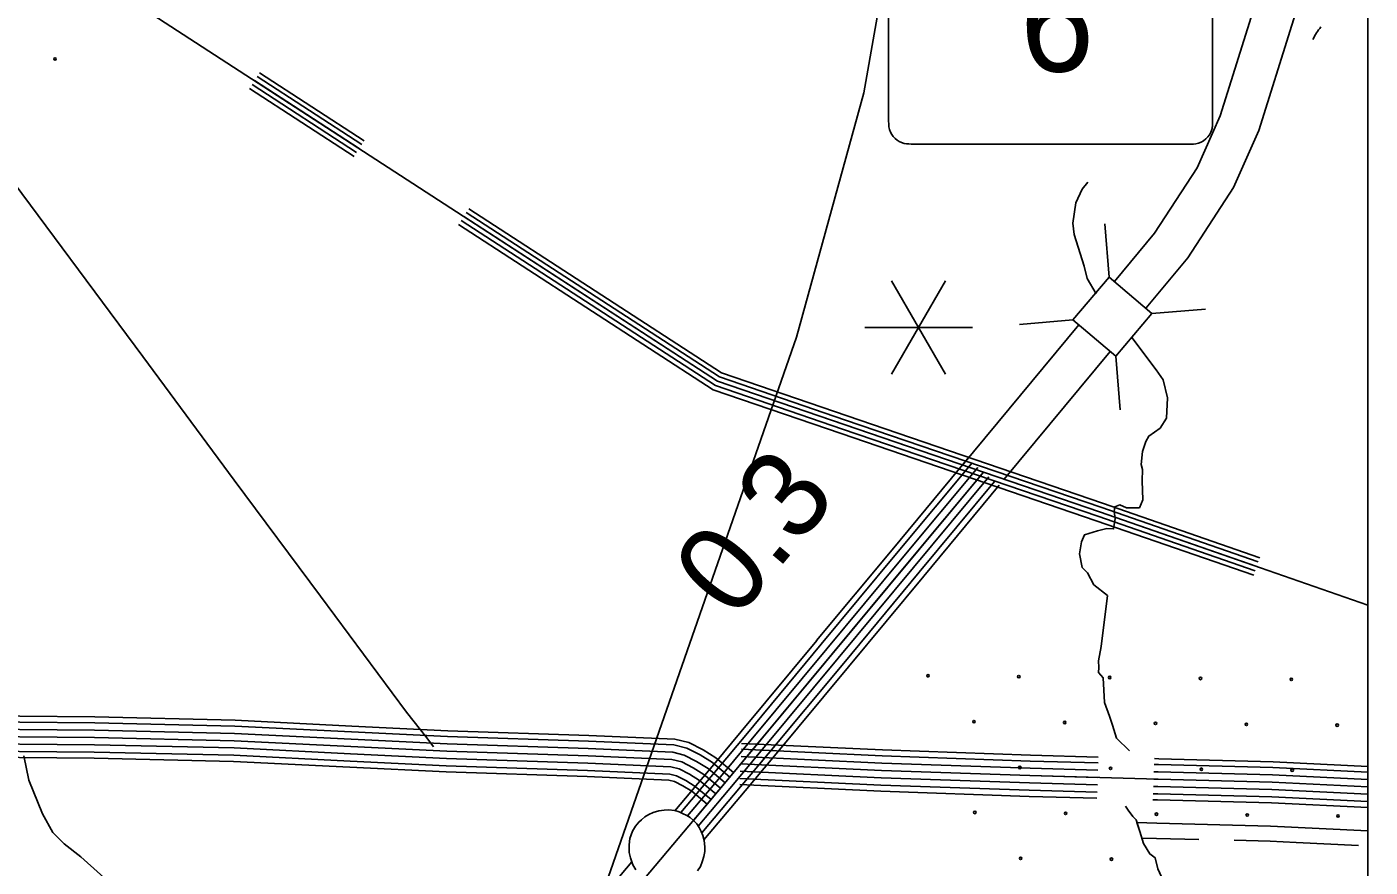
# Model space of a CAD drawing. Extents: x 1577619 to 1828281, y 483481 to 598136.
# Drawn here: x 1689939 to 1695627, y 517507 to 521065 of the extents above; entities that cross this region are included whole.
import ezdxf

# ---------------------------------------------------------------- set-up
doc = ezdxf.new("R2010")
doc.units = 0
for name, color, linetype in [('DESIGN - EROSION CONTROL - Devices', 7, 'Continuous'), ('DESIGN - ROW - Slope Lines', 7, 'Continuous'), ('DESIGN - SHEET - Linework', 7, 'Continuous'), ('DESIGN - TRAFFIC CONTROL PERMANENT - Signalization', 7, 'Continuous'), ('DESIGN - TRANSPORTATION - Text', 7, 'Continuous'), ('SURVEY - CENTERLINE - Preliminary', 7, 'Continuous'), ('SURVEY - CENTERLINE - Preliminary Text', 7, 'Continuous'), ('SURVEY - CONTROL with Text', 7, 'Continuous'), ('SURVEY - DRAINAGE - Area Shapes', 7, 'Continuous'), ('SURVEY - DRAINAGE - Bridge Deck with Text', 7, 'Continuous'), ('SURVEY - DRAINAGE - Natural Features', 7, 'Continuous'), ('SURVEY - DRAINAGE - Storm Sewer', 7, 'Continuous'), ('SURVEY - VEGETATION - Features with Text', 7, 'Continuous')]:
    doc.layers.add(name, color=color, linetype=linetype)

msp = doc.modelspace()

# ---------------------------------------------------------------- linework, layer by layer
at = {"layer": 'DESIGN - EROSION CONTROL - Devices'}
for centre in [(1690058, 520929.4), (1693755.1, 518317.3), (1694139.6, 518313.6), (1694524.2, 518309.8), (1694908.7, 518306.1), (1695293.3, 518302.4), (1693949.2, 518123.1), (1694333.8, 518119.4), (1694718.3, 518115.7), (1695102.9, 518111.9), (1695487.4, 518108.2), (1694143.4, 517929), (1694527.9, 517925.3), (1694912.5, 517921.5), (1695297, 517917.8), (1693953, 517738.6), (1694337.5, 517734.9), (1694722.1, 517731.1), (1695106.6, 517727.4), (1695491.2, 517723.7), (1694147.1, 517544.4), (1694531.6, 517540.7)]:
    msp.add_circle(centre, 5.28, dxfattribs=at)
at = {"layer": 'DESIGN - ROW - Slope Lines'}
for p, q in [((1693587.2, 521509.8), (1693587.2, 520678.1)), ((1694960.1, 520679.5), (1694960.1, 521499.4)), ((1693693.6, 520568.7), (1694850.2, 520568.7))]:
    msp.add_line(p, q, dxfattribs=at)
for centre, radius, start, end in [((1693861.3, 520677.3), 274.1, 179.8528, 189.8964), ((1694013, 520684.2), 947.1, 357.7373, 359.7128), ((1693677.9, 520659.3), 91.3, 198.5724, 254.4318), ((1694871.7, 520657.1), 89.4, 280.9255, 342.7446), ((1694890.7, 520648.3), 68.6, 345.0701, 358.7436), ((1693697.5, 520931.1), 362.4, 263.0109, 269.3986), ((1694860.7, 521103.5), 534.8, 268.8795, 272.9943)]:
    msp.add_arc(centre, radius, start, end, dxfattribs=at)
at = {"layer": 'DESIGN - SHEET - Linework'}
msp.add_lwpolyline([(1669171.5, 526510.7), (1695618, 526510.7), (1695618, 508119.9), (1669171.5, 508119.9)], close=True, dxfattribs=at)
at = {"layer": 'DESIGN - TRAFFIC CONTROL PERMANENT - Signalization'}
for q in [(1693600.8, 519989.3), (1693828.9, 519989.3), (1693486.8, 519791.7), (1693600.8, 519594.2), (1693942.9, 519791.8), (1693828.9, 519594.2)]:
    msp.add_line((1693714.9, 519791.7), q, dxfattribs=at)
at = {"layer": 'DESIGN - TRANSPORTATION - Text'}
for points in [[(1694466.6, 519935.3), (1694428.4, 519999.1), (1694416.4, 520051.7), (1694382.9, 520159.5), (1694373.4, 520185.8), (1694368.6, 520233.7), (1694380.5, 520319.9), (1694406.9, 520377.4), (1694432.1, 520407.7)], [(1694514.5, 518657.9), (1694457.3, 518702.9), (1694429.8, 518753.4), (1694408, 518775.8), (1694396.7, 518834.2), (1694405.3, 518884.2), (1694417.7, 518914.2), (1694472, 518931.6), (1694512.3, 518941.2), (1694540.3, 518938.9), (1694546.9, 518982.9), (1694543.2, 519013.1), (1694545.5, 519033.2), (1694567.6, 519040.9), (1694595.6, 519028.5), (1694625.7, 519028.2), (1694649.7, 519027.9), (1694664.2, 519061.8), (1694661.1, 519142.2), (1694663.7, 519190.4), (1694657.9, 519212.5), (1694662.6, 519266.7), (1694677.1, 519308.7), (1694689.5, 519332.6), (1694738, 519366.2), (1694764.6, 519408), (1694769.2, 519493.8), (1694750.1, 519570.4), (1694721.4, 519613.5), (1694617.8, 519749.4)], [(1694514.5, 518657.9), (1694487.7, 518441.8), (1694476.8, 518380), (1694478.7, 518352.8), (1694476.3, 518331.2), (1694496.1, 518308.9), (1694502.7, 518204.1), (1694522.7, 518146), (1694535.4, 518107.9), (1694553.6, 518053.4), (1694608, 517999.2)], [(1689925.9, 517977.9), (1689946.8, 517875.4), (1690005.3, 517732.4), (1690048.5, 517653.7), (1690096, 517605.1), (1690167.5, 517550.2), (1690320.1, 517414.2)], [(1694591, 517765.1), (1694602.2, 517748.3), (1694621.9, 517722), (1694635.8, 517707.8), (1694651.3, 517657.5), (1694666.8, 517607.2), (1694694.3, 517562.8), (1694716.1, 517546.5), (1694727.7, 517500.3)]]:
    msp.add_lwpolyline(points, dxfattribs=at)
at = {"layer": 'SURVEY - CENTERLINE - Preliminary'}
for points in [[(1699664.1, 538980.8), (1699319.1, 538409.9), (1698972.3, 537842.5), (1695481.3, 532468.9), (1695357.3, 532233.8), (1695216.5, 531898.8), (1695066.9, 531469.7), (1694585.2, 529330), (1694371.3, 528155.8), (1694207.2, 527174.4), (1693664.5, 521961.3), (1693575.1, 521307.5), (1693482.8, 520785.8), (1693198.2, 519751.4), (1691958.7, 516195.2)], [(1699664.1, 538980.8), (1699319.1, 538409.9), (1698972.3, 537842.5), (1695481.3, 532468.9), (1695357.3, 532233.8), (1695216.5, 531898.8), (1695066.9, 531469.7), (1694585.2, 529330), (1694371.3, 528155.8), (1694207.2, 527174.4), (1693664.5, 521961.3), (1693575.1, 521307.5), (1693482.8, 520785.8), (1693198.2, 519751.4), (1691958.7, 516195.2)], [(1694138.1, 526510.7), (1693664.5, 521961.3), (1693575.1, 521307.5), (1693482.8, 520785.8), (1693198.2, 519751.4), (1691958.7, 516195.2)], [(1694138.1, 526510.7), (1693664.5, 521961.3), (1693575.1, 521307.5), (1693482.8, 520785.8), (1693198.2, 519751.4), (1691958.7, 516195.2)]]:
    msp.add_lwpolyline(points, dxfattribs=at)
at = {"layer": 'SURVEY - CENTERLINE - Preliminary Text'}
for points in [[(1695269.4, 521574.5), (1694992.2, 520687.8), (1694894.5, 520468.7), (1694713.7, 520191.2), (1694544.4, 519986.7)], [(1695434.9, 521519.3), (1695155.6, 520626), (1695048.2, 520385), (1694854.4, 520087.6), (1694679.2, 519876)], [(1694392.8, 519803.6), (1693899.1, 519207.3)], [(1694525.6, 519690.5), (1694077.9, 519149.7)], [(1693922.4, 519235.5), (1693602.8, 518851)], [(1693941.4, 519219.7), (1693621.8, 518835.2)], [(1693965.3, 519199.9), (1693645.7, 518815.4)], [(1693989.1, 519180.1), (1692913.8, 517886.3), (1692164.4, 516995.8)], [(1693989.1, 519180.1), (1693669.5, 518795.5)], [(1694013, 519160.2), (1693693.4, 518775.7)], [(1694036.8, 519140.4), (1693717.2, 518755.9)], [(1694056.6, 519124), (1693737, 518739.5)], [(1693602.9, 518851), (1693283.2, 518466.5)], [(1693621.9, 518835.2), (1693302.3, 518450.7)], [(1693645.7, 518815.4), (1693326.1, 518430.9)], [(1693669.5, 518795.6), (1693349.9, 518411)], [(1693693.4, 518775.7), (1693373.8, 518391.2)], [(1693717.2, 518755.9), (1693397.6, 518371.4)], [(1693737, 518739.5), (1693417.4, 518355)], [(1693283.3, 518466.5), (1692963.7, 518082)], [(1693302.3, 518450.7), (1692982.7, 518066.2)], [(1693326.1, 518430.9), (1693006.5, 518046.3)], [(1693349.9, 518411), (1693030.3, 518026.5)], [(1693373.8, 518391.2), (1693054.2, 518006.7)], [(1693397.6, 518371.4), (1693078, 517986.9)], [(1693417.4, 518355), (1693097.8, 517970.5)], [(1692963.7, 518082), (1692847.2, 517941.9), (1692682.4, 517746)], [(1692982.7, 518066.2), (1692866.2, 517926), (1692708.3, 517738.4)], [(1693006.5, 518046.4), (1692890, 517906.2), (1692736.5, 517723.8)], [(1693030.3, 518026.5), (1692913.8, 517886.3), (1692761.1, 517704.8)], [(1693054.2, 518006.7), (1692937.5, 517866.4), (1692781, 517680.4)], [(1693078, 517986.9), (1692961.3, 517846.5), (1692797.5, 517651.8)], [(1693097.8, 517970.5), (1692981, 517830), (1692806, 517622)], [(1692500.2, 517529.5), (1692321, 517316.6)]]:
    msp.add_lwpolyline(points, dxfattribs=at)
at = {"layer": 'SURVEY - CONTROL with Text'}
for points in [[(1680622.4, 518118.1), (1681890.1, 518100.2), (1682947.2, 518086.3), (1684160.8, 518074.9), (1685440.5, 518054.8), (1685817.6, 518049.3), (1686277.1, 518055), (1686923.1, 518057), (1687797.8, 518056.8), (1688568.2, 518065.6), (1689589.4, 518062.1), (1690225.2, 518056.1), (1690816.9, 518042.5), (1691310.2, 518017.8), (1691717.2, 517997.9), (1692314.9, 517978.2), (1692669.8, 517962.9), (1692711.8, 517952.4), (1692759.7, 517927.9), (1692805.6, 517899.3), (1692875.5, 517840.9)], [(1687034.2, 518143.7), (1687797.3, 518143.5), (1688567.9, 518152.3), (1689589.9, 518148.8), (1690226.6, 518142.8), (1690820.1, 518129.2), (1691314.5, 518104.4), (1691720.8, 518084.6), (1692318.2, 518064.9), (1692682.2, 518049.1), (1692742.4, 518034.2), (1692802.5, 518003.4), (1692856.5, 517969.8), (1692931.1, 517907.4)], [(1687034.6, 518119), (1687797.4, 518118.8), (1688568, 518127.6), (1689589.8, 518124.1), (1690226.2, 518118.1), (1690819.2, 518104.5), (1691313.3, 518079.7), (1691719.8, 518059.9), (1692317.2, 518040.2), (1692678.7, 518024.5), (1692733.7, 518010.9), (1692790.3, 517981.9), (1692842, 517949.7), (1692915.3, 517888.4)], [(1687035.2, 518088), (1687797.6, 518087.8), (1688568.1, 518096.6), (1689589.6, 518093.1), (1690225.7, 518087.1), (1690818.1, 518073.5), (1691311.7, 518048.7), (1691718.5, 518028.9), (1692316, 518009.2), (1692674.2, 517993.7), (1692722.8, 517981.6), (1692775, 517954.9), (1692823.8, 517924.5), (1692895.4, 517864.6)], [(1687035.7, 518056.9), (1687797.8, 518056.8), (1688568.2, 518065.6), (1689589.4, 518062.1), (1690225.2, 518056.1), (1690816.9, 518042.5), (1691310.2, 518017.8), (1691717.2, 517997.9), (1692314.9, 517978.2), (1692669.8, 517962.9), (1692711.8, 517952.4), (1692759.7, 517927.9), (1692805.6, 517899.3), (1692875.5, 517840.9)], [(1687036.3, 518025.9), (1687798, 518025.8), (1688568.4, 518034.6), (1689589.2, 518031), (1690224.7, 518025.1), (1690815.8, 518011.5), (1691308.7, 517986.8), (1691716, 517966.9), (1692313.7, 517947.3), (1692665.3, 517932), (1692700.9, 517923.2), (1692744.4, 517900.9), (1692787.4, 517874.2), (1692855.7, 517817.1)], [(1687036.8, 517994.9), (1687798.1, 517994.8), (1688568.5, 518003.6), (1689588.9, 518000), (1690224.2, 517994.1), (1690814.7, 517980.5), (1691307.1, 517955.9), (1691714.7, 517935.9), (1692312.5, 517916.3), (1692660.9, 517901.2), (1692689.9, 517894), (1692729.1, 517873.9), (1692769.1, 517849), (1692835.8, 517793.3)], [(1692964.3, 518006.1), (1693560.6, 517978.3), (1694187.7, 517956.4), (1694475.1, 517948.4)], [(1692965.5, 518030.8), (1693561.6, 518003), (1694188.5, 517981.1), (1694476, 517973.1)], [(1687037.3, 517969.2), (1687798.3, 517969.1), (1688568.6, 517977.9), (1689588.8, 517974.3), (1690223.8, 517968.4), (1690813.7, 517954.8), (1691305.9, 517930.2), (1691713.7, 517910.2), (1692311.5, 517890.6), (1692657.2, 517875.6), (1692680.8, 517869.7), (1692716.5, 517851.5), (1692754, 517828.1), (1692819.3, 517773.5)], [(1692961.4, 517944.2), (1693558, 517916.4), (1694185.8, 517894.4), (1694729.3, 517879.3), (1695212.6, 517866.7), (1695618, 517847)], [(1692961.4, 517944.2), (1693558, 517916.4), (1694185.8, 517894.4), (1694473, 517886.4)], [(1692962.9, 517975.1), (1693559.3, 517947.3), (1694186.7, 517925.4), (1694474, 517917.4)], [(1694712.6, 517941.8), (1694730.9, 517941.2), (1695214.9, 517928.7), (1695618, 517909)], [(1694713.5, 517966.5), (1694731.6, 517966), (1695215.9, 517953.4), (1695618, 517933.8)], [(1692958.5, 517882.2), (1693555.5, 517854.4), (1694183.8, 517832.4), (1694470.8, 517824.4)], [(1692960, 517913.2), (1693556.8, 517885.4), (1694184.8, 517863.4), (1694471.9, 517855.4)], [(1694711.6, 517910.8), (1694730.1, 517910.3), (1695213.8, 517897.7), (1695618, 517878)], [(1692957.3, 517856.5), (1693554.5, 517828.7), (1694183, 517806.7), (1694469.9, 517798.7)], [(1694709.4, 517848.8), (1694728.4, 517848.3), (1695211.5, 517835.7), (1695618, 517815.9)], [(1694710.5, 517879.8), (1694729.3, 517879.3), (1695212.6, 517866.7), (1695618, 517847)], [(1694707.4, 517792.1), (1694726.9, 517791.6), (1695209.4, 517779), (1695618, 517759.1)], [(1694708.3, 517817.8), (1694727.6, 517817.3), (1695210.3, 517804.7), (1695618, 517784.9)]]:
    msp.add_lwpolyline(points, dxfattribs=at)
at = {"layer": 'SURVEY - DRAINAGE - Area Shapes'}
msp.add_lwpolyline([(1689617.1, 520943.1), (1689600.8, 520919.2), (1689592.6, 520897.3), (1689586.3, 520869.3), (1689586, 520839.2), (1689589.5, 520799), (1689600.6, 520772.2), (1689638.8, 520726.3), (1689814.5, 520495.9), (1690430.1, 519669.2), (1690816.8, 519145.7), (1691181.8, 518654.5), (1691546.8, 518163.4), (1691631.7, 518054.2), (1691660.1, 518016.4)], dxfattribs=at)
at = {"layer": 'SURVEY - DRAINAGE - Bridge Deck with Text'}
msp.add_arc((1695595.1, 520916.1), 230.9, 139.7936, 155.7263, dxfattribs=at)
at = {"layer": 'SURVEY - DRAINAGE - Natural Features'}
for points in [[(1690050.6, 521391.1), (1692863.1, 519564.5), (1694480.4, 519011.9), (1695618, 518616.9)], [(1690050.6, 521391.1), (1692863.1, 519564.5), (1694480.4, 519011.9), (1695618, 518616.9)], [(1690913.9, 520854.3), (1691356.7, 520566.7)], [(1690924.3, 520870.2), (1691367.1, 520582.6)], [(1690881.3, 520804), (1691324.1, 520516.4)], [(1690892.2, 520820.7), (1691335, 520533.1)], [(1690903, 520837.5), (1691345.8, 520549.9)], [(1691799.5, 520279.1), (1692872, 519582.6), (1693405.9, 519400.2)], [(1691809.9, 520295.1), (1692880.3, 519599.8), (1693412.1, 519418.2)], [(1691766.9, 520228.8), (1692845.5, 519528.2), (1693386.5, 519343.4)], [(1691777.8, 520245.6), (1692854.3, 519546.4), (1693393, 519362.3)], [(1691788.7, 520262.3), (1692863.1, 519564.5), (1693399.5, 519381.3)], [(1693412.1, 519418.2), (1694493.1, 519048.8), (1695159.8, 518817.3)], [(1693393, 519362.3), (1694473.8, 518993), (1695140.5, 518761.6)], [(1693399.5, 519381.3), (1694480.4, 519011.9), (1695147, 518780.4)], [(1693405.9, 519400.2), (1694486.9, 519030.9), (1695153.6, 518799.3)], [(1693386.5, 519343.4), (1694467.3, 518974.1), (1695133.9, 518742.7)]]:
    msp.add_lwpolyline(points, dxfattribs=at)
at = {"layer": 'SURVEY - DRAINAGE - Storm Sewer'}
for p, q in [((1694521.9, 520005.3), (1694503.3, 520231.6)), ((1694368.3, 519824), (1694141.9, 519805.4)), ((1694703.2, 519851.7), (1694929.5, 519870.4)), ((1694549.6, 519670.4), (1694568.2, 519444))]:
    msp.add_line(p, q, dxfattribs=at)
msp.add_lwpolyline([(1694521.9, 520005.3), (1694368.2, 519824), (1694549.6, 519670.4), (1694703.2, 519851.7)], close=True, dxfattribs=at)
at = {"layer": 'SURVEY - VEGETATION - Features with Text'}
for points in [[(1692517, 517495.1), (1692504.9, 517516.2), (1692494.6, 517547), (1692488.8, 517568.6), (1692489.5, 517601.9), (1692492, 517628.3), (1692503.6, 517659), (1692515.8, 517680.1), (1692529.9, 517697.4), (1692541.3, 517707.7), (1692556, 517720), (1692572.7, 517729.5), (1692591.4, 517738.3), (1692615, 517746), (1692637.3, 517748.7), (1692655.3, 517749.4), (1692682.2, 517746.1), (1692700.8, 517740.9), (1692715.6, 517734.5), (1692732.9, 517725.6), (1692746.9, 517716.5), (1692761.7, 517704.5), (1692775.1, 517689.8), (1692785.3, 517674.2), (1692793.6, 517657.6), (1692801.9, 517641), (1692807.1, 517619.9), (1692809.7, 517592.5), (1692809, 517573.3), (1692805.8, 517552), (1692798.7, 517529.6), (1692791.8, 517509.9), (1692778.4, 517491.9)], [(1694639.5, 517695.8), (1694724.3, 517693.4), (1695205.7, 517680.9), (1695618, 517660.8)], [(1694639.5, 517695.8), (1694651.3, 517657.5), (1694666.8, 517607.2), (1694694.3, 517562.8), (1694716.1, 517546.5), (1694727.7, 517500.3), (1694751.1, 517449.9), (1694780.6, 517401.5), (1694808.2, 517361.1), (1694822.1, 517342.9), (1694829.9, 517328.8), (1694823.8, 517314.8), (1694813.6, 517300.8), (1694791.5, 517297.1), (1694775.4, 517283.2), (1694771.3, 517273.2), (1694763, 517249.2), (1694782.8, 517227), (1694808.7, 517214.7), (1694848.6, 517204.2), (1694870.5, 517198), (1694867.4, 517089.7), (1694835.9, 516945.6)], [(1694659.7, 517630.3), (1694722.5, 517628.5), (1694901.7, 517623.9)], [(1694659.7, 517630.3), (1694666.8, 517607.2), (1694694.3, 517562.8), (1694716.1, 517546.5), (1694727.7, 517500.3), (1694746.3, 517460.2)], [(1695051.7, 517620.6), (1695203.3, 517616.6), (1695314, 517611.2)], [(1695314.1, 517611.9), (1695577.8, 517599)]]:
    msp.add_lwpolyline(points, dxfattribs=at)

# ---------------------------------------------------------------- texts
at = {"layer": 'DESIGN - ROW - Slope Lines'}
msp.add_text('6', height=422.4, rotation=0.0013, dxfattribs=at).set_placement((1694144.4, 520875.8))
at = {"layer": 'DESIGN - TRAFFIC CONTROL PERMANENT - Signalization'}
msp.add_text('0.3', height=370, rotation=50.2669, dxfattribs=at).set_placement((1692936.3, 518545))

doc.saveas('drawing.dxf')
